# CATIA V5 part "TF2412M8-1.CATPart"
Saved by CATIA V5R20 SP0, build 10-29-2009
Part number: TF2412M8-1
Revision: ANY
Definition: UNKNOWN
Nomenclature: TF2412M8-1
Source: Unknown
Bounding box of the stored display mesh (mm): x -5.801 to 5.801, y 0 to 27.45, z -5.95 to 5.95
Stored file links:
  C:\Users\Utente\Desktop\IO LAVORO\3D X SITO CF\CUMSA\3D files RCM\RCM 245712\TF2412M8-1.CATPart
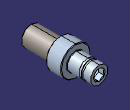
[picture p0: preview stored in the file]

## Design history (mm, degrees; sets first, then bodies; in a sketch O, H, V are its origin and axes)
Body1 "Chaflán2" (main body)
  Solid1: solid without history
